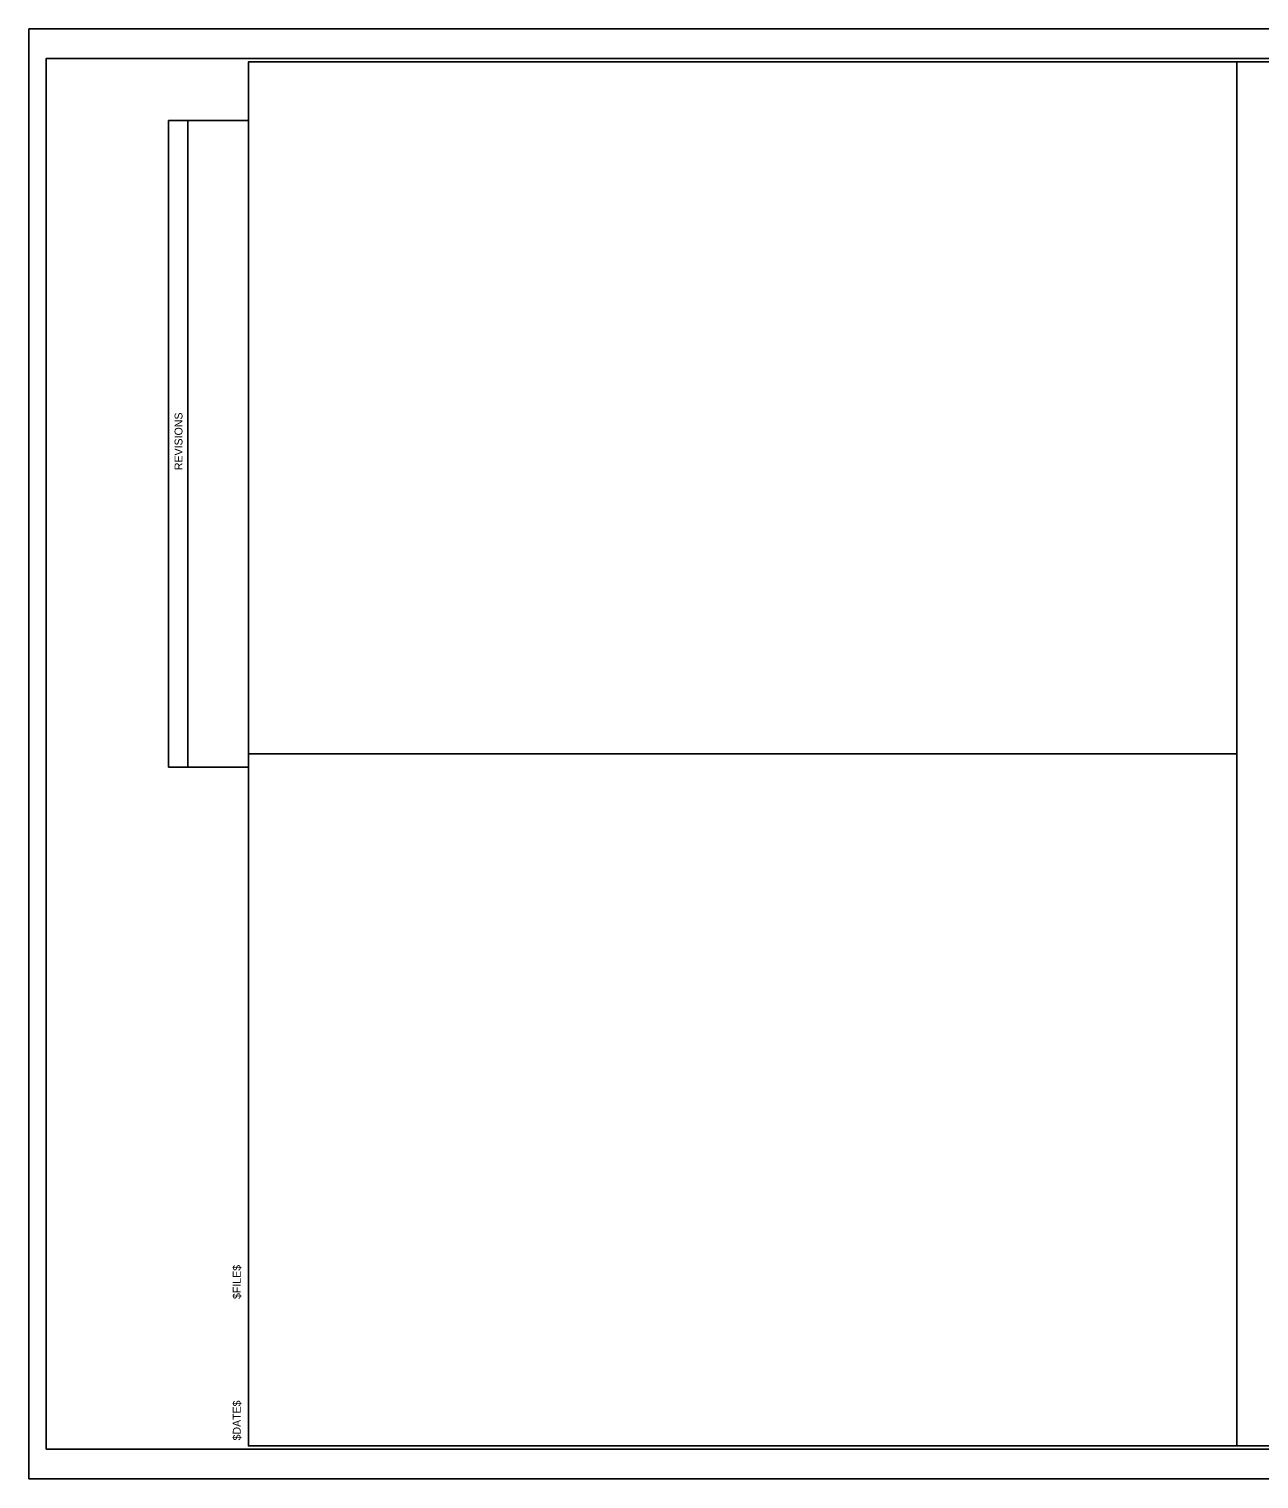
# Model space of a CAD drawing. Extents: x 2431000 to 2534000, y 645879 to 714000.
# Drawn here: x 2464841 to 2465774, y 661273 to 662373 of the extents above; entities that cross this region are included whole.
import ezdxf

# ---------------------------------------------------------------- set-up
doc = ezdxf.new("R2010")
doc.units = 0
for name, color, linetype in [('Old_Level_2', 7, 'Continuous'), ('Prop Dimension', 7, 'Continuous'), ('Prop Dimension Text', 7, 'Continuous'), ('Prop Shade Light', 7, 'Continuous'), ('Prop Terminator CELL', 7, 'Continuous')]:
    doc.layers.add(name, color=color, linetype=linetype)

msp = doc.modelspace()

# ---------------------------------------------------------------- linework, layer by layer
at = {"layer": 'Old_Level_2'}
for p, q in [((2465757.2, 662348.5), (2465757.2, 661298.5)), ((2465007.2, 661823.5), (2465757.2, 661823.5)), ((2465007.2, 661298.5), (2465007.2, 661298.5)), ((2465007.2, 661298.5), (2465007.2, 661298.5)), ((2465007.2, 661298.5), (2465007.2, 661298.5)), ((2465007.2, 661298.5), (2465007.2, 661298.5)), ((2465007.2, 661298.5), (2465007.2, 661298.5)), ((2465007.2, 661298.5), (2465007.2, 661298.5))]:
    msp.add_line(p, q, dxfattribs=at)
msp.add_lwpolyline([(2466507.2, 662348.5), (2465007.2, 662348.5), (2465007.2, 661298.5), (2466507.2, 661298.5)], close=True, dxfattribs=at)
msp.add_lwpolyline([(2465044.7, 661298.5), (2465044.7, 661298.5)], dxfattribs=at)
at = {"layer": 'Prop Dimension'}
msp.add_lwpolyline([(2464840.7, 661273.5), (2466524.2, 661273.5), (2466524.2, 662373.5), (2464840.7, 662373.5)], close=True, dxfattribs=at)
at = {"layer": 'Prop Shade Light'}
for p, q in [((2464946.7, 661813.4), (2464946.7, 662304.1)), ((2465007.2, 662304.1), (2464946.7, 662304.1)), ((2464961.3, 661813.4), (2464961.2, 662304.1)), ((2465007.2, 661813.4), (2464946.7, 661813.4))]:
    msp.add_line(p, q, dxfattribs=at)
at = {"layer": 'Prop Terminator CELL'}
msp.add_lwpolyline([(2464853.7, 661296), (2466519.7, 661296), (2466519.7, 662351), (2464853.7, 662351)], close=True, dxfattribs=at)

# ---------------------------------------------------------------- texts
at = {"layer": 'Prop Dimension Text'}
for s, p in [('$FILE$', (2465001.4, 661410)), ('$DATE$', (2465001.4, 661302.7))]:
    msp.add_text(s, height=6, rotation=90, dxfattribs=at).set_placement(p)
at = {"layer": 'Prop Shade Light'}
msp.add_text('REVISIONS', height=6, rotation=90, dxfattribs=at).set_placement((2464957.2, 662038.8))

doc.saveas('drawing.dxf')
